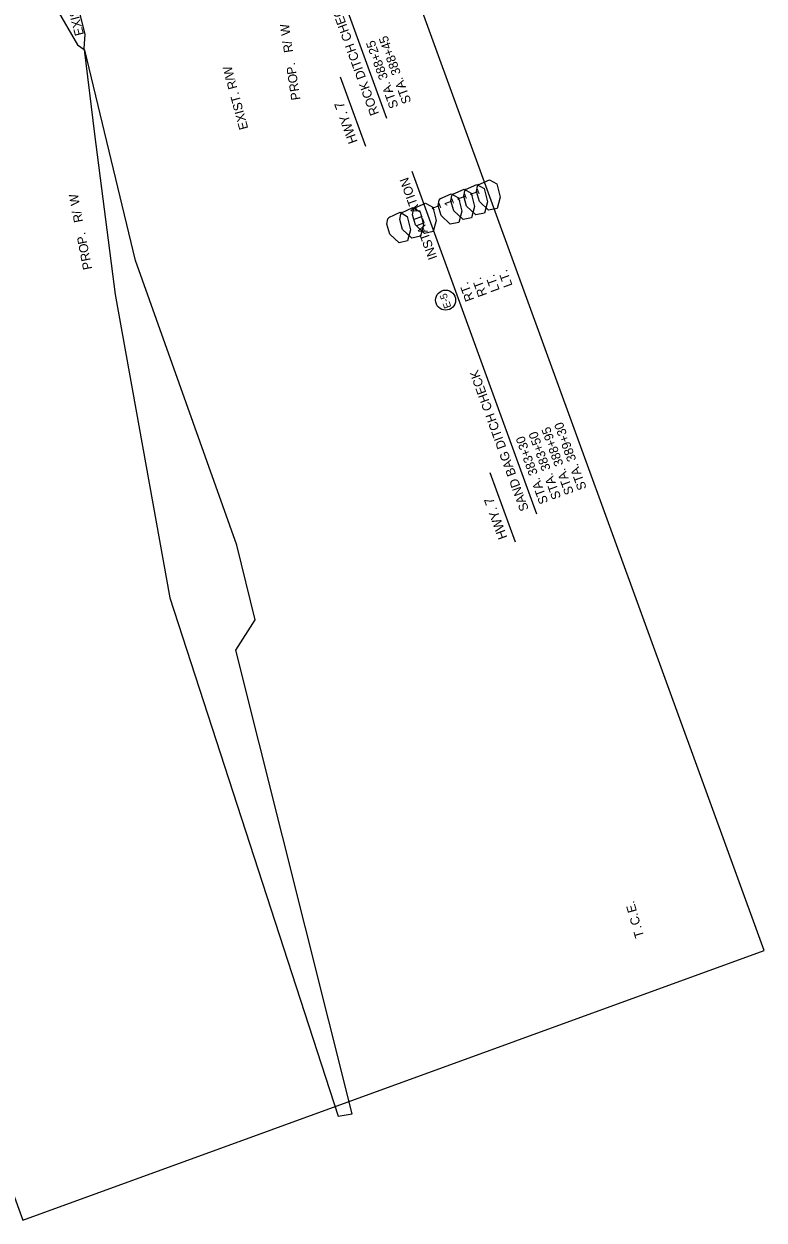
# Model space of a CAD drawing. Extents: x 960650 to 962115, y 1906901 to 1908930.
# Drawn here: x 961626 to 962115, y 1907079 to 1907870 of the extents above; entities that cross this region are included whole.
import ezdxf

# ---------------------------------------------------------------- set-up
doc = ezdxf.new("R2010")
doc.units = 0
for name, color, linetype in [('1', 7, 'Continuous'), ('44', 7, 'Continuous'), ('NO PLOT', 7, 'Continuous'), ('R_Draft', 7, 'Continuous'), ('S_TREE', 7, 'Continuous')]:
    doc.layers.add(name, color=color, linetype=linetype)

msp = doc.modelspace()

# ---------------------------------------------------------------- linework, layer by layer
at = {"layer": '1'}
msp.add_circle((961904.14, 1907687.38), 6.61, dxfattribs=at)
at = {"layer": '44'}
for p, q in [((961865.4, 1907807.44), (961782.97, 1908033.91)), ((961851.33, 1907788.82), (961834.62, 1907834.72)), ((961964.38, 1907545.95), (961881.95, 1907772.42)), ((961950.3, 1907527.33), (961933.6, 1907573.23))]:
    msp.add_line(p, q, dxfattribs=at)
at = {"layer": 'NO PLOT'}
msp.add_lwpolyline([(962114.55, 1907257.7), (961568.91, 1908756.85), (961079.18, 1908578.6), (961182.12, 1908295.76), (961245.55, 1908318.85), (961390.91, 1907919.48), (961327.48, 1907896.39), (961425.36, 1907627.47), (961483.4, 1907648.6), (961600.59, 1907326.6), (961542.56, 1907305.48), (961624.82, 1907079.46)], close=True, dxfattribs=at)
msp.add_lwpolyline([(962114.55, 1907257.7), (961568.91, 1908756.85), (961079.18, 1908578.6), (961182.12, 1908295.76), (961245.55, 1908318.85), (961390.91, 1907919.48), (961327.48, 1907896.39), (961425.36, 1907627.47), (961483.4, 1907648.6), (961600.59, 1907326.6), (961542.56, 1907305.48), (961624.82, 1907079.46)], close=True, dxfattribs=at)
msp.add_lwpolyline([(962114.55, 1907257.7), (961568.91, 1908756.85), (961079.18, 1908578.6), (961182.12, 1908295.76), (961245.55, 1908318.85), (961390.91, 1907919.48), (961327.48, 1907896.39), (961425.36, 1907627.47), (961483.4, 1907648.6), (961600.59, 1907326.6), (961542.56, 1907305.48), (961624.82, 1907079.46)], close=True, dxfattribs=at)
msp.add_lwpolyline([(961546.11, 1908053.77), (961660.88, 1907856.14), (961665.4, 1907852.91), (961665.4, 1907852.91), (961672.08, 1907797.08), (961685.77, 1907691.1), (961721.87, 1907490.67), (961833.17, 1907148.06), (961842.49, 1907149.72), (961765.53, 1907456.14), (961778.4, 1907476.17), (961766.21, 1907525.48), (961699.17, 1907713.63), (961665.82, 1907852.62), (961665.4, 1907852.91), (961665.4, 1907852.91), (961665.39, 1907852.96), (961665.26, 1907853.71), (961666.04, 1907863.2), (961658.05, 1907894.81)], dxfattribs=at)
at = {"layer": 'S_TREE'}
for points in [[(961908.82, 1907757.31), (961916.29, 1907760.79), (961921.12, 1907758.06), (961923.27, 1907749.23), (961921.34, 1907741.85), (961915.63, 1907740.58), (961909.55, 1907746.46), (961907.7, 1907752.91), (961908.31, 1907756.56), (961909.5, 1907757.78)], [(961908.82, 1907757.31), (961916.29, 1907760.79), (961921.12, 1907758.06), (961923.27, 1907749.23), (961921.34, 1907741.85), (961915.63, 1907740.58), (961909.55, 1907746.46), (961907.7, 1907752.91), (961908.31, 1907756.56), (961909.5, 1907757.78)], [(961908.82, 1907757.31), (961916.29, 1907760.79), (961921.12, 1907758.06), (961923.27, 1907749.23), (961921.34, 1907741.85), (961915.63, 1907740.58), (961909.55, 1907746.46), (961907.7, 1907752.91), (961908.31, 1907756.56), (961909.5, 1907757.78)], [(961908.82, 1907757.31), (961916.29, 1907760.79), (961921.12, 1907758.06), (961923.27, 1907749.23), (961921.34, 1907741.85), (961915.63, 1907740.58), (961909.55, 1907746.46), (961907.7, 1907752.91), (961908.31, 1907756.56), (961909.5, 1907757.78)], [(961917.28, 1907760.39), (961924.75, 1907763.87), (961929.58, 1907761.14), (961931.73, 1907752.31), (961929.79, 1907744.93), (961924.09, 1907743.66), (961918.01, 1907749.54), (961916.15, 1907755.99), (961916.77, 1907759.64), (961917.96, 1907760.86)], [(961917.28, 1907760.39), (961924.75, 1907763.87), (961929.58, 1907761.14), (961931.73, 1907752.31), (961929.79, 1907744.93), (961924.09, 1907743.66), (961918.01, 1907749.54), (961916.15, 1907755.99), (961916.77, 1907759.64), (961917.96, 1907760.86)], [(961917.28, 1907760.39), (961924.75, 1907763.87), (961929.58, 1907761.14), (961931.73, 1907752.31), (961929.79, 1907744.93), (961924.09, 1907743.66), (961918.01, 1907749.54), (961916.15, 1907755.99), (961916.77, 1907759.64), (961917.96, 1907760.86)], [(961917.28, 1907760.39), (961924.75, 1907763.87), (961929.58, 1907761.14), (961931.73, 1907752.31), (961929.79, 1907744.93), (961924.09, 1907743.66), (961918.01, 1907749.54), (961916.15, 1907755.99), (961916.77, 1907759.64), (961917.96, 1907760.86)], [(961925.73, 1907763.46), (961933.21, 1907766.95), (961938.04, 1907764.22), (961940.19, 1907755.39), (961938.25, 1907748.01), (961932.55, 1907746.73), (961926.47, 1907752.62), (961924.61, 1907759.06), (961925.22, 1907762.72), (961926.42, 1907763.94)], [(961925.73, 1907763.46), (961933.21, 1907766.95), (961938.04, 1907764.22), (961940.19, 1907755.39), (961938.25, 1907748.01), (961932.55, 1907746.73), (961926.47, 1907752.62), (961924.61, 1907759.06), (961925.22, 1907762.72), (961926.42, 1907763.94)], [(961900.36, 1907754.23), (961907.84, 1907757.72), (961912.66, 1907754.98), (961914.81, 1907746.15), (961912.88, 1907738.77), (961907.18, 1907737.5), (961901.1, 1907743.38), (961899.24, 1907749.83), (961899.85, 1907753.48), (961901.04, 1907754.71)], [(961900.36, 1907754.23), (961907.84, 1907757.72), (961912.66, 1907754.98), (961914.81, 1907746.15), (961912.88, 1907738.77), (961907.18, 1907737.5), (961901.1, 1907743.38), (961899.24, 1907749.83), (961899.85, 1907753.48), (961901.04, 1907754.71)], [(961900.36, 1907754.23), (961907.84, 1907757.72), (961912.66, 1907754.98), (961914.81, 1907746.15), (961912.88, 1907738.77), (961907.18, 1907737.5), (961901.1, 1907743.38), (961899.24, 1907749.83), (961899.85, 1907753.48), (961901.04, 1907754.71)], [(961900.36, 1907754.23), (961907.84, 1907757.72), (961912.66, 1907754.98), (961914.81, 1907746.15), (961912.88, 1907738.77), (961907.18, 1907737.5), (961901.1, 1907743.38), (961899.24, 1907749.83), (961899.85, 1907753.48), (961901.04, 1907754.71)], [(961866.53, 1907741.92), (961874.01, 1907745.4), (961878.84, 1907742.67), (961880.98, 1907733.84), (961879.05, 1907726.46), (961873.35, 1907725.19), (961867.27, 1907731.07), (961865.41, 1907737.52), (961866.02, 1907741.17), (961867.22, 1907742.39)], [(961866.53, 1907741.92), (961874.01, 1907745.4), (961878.84, 1907742.67), (961880.98, 1907733.84), (961879.05, 1907726.46), (961873.35, 1907725.19), (961867.27, 1907731.07), (961865.41, 1907737.52), (961866.02, 1907741.17), (961867.22, 1907742.39)], [(961874.99, 1907745), (961882.46, 1907748.48), (961887.29, 1907745.75), (961889.44, 1907736.92), (961887.51, 1907729.54), (961881.8, 1907728.27), (961875.72, 1907734.15), (961873.87, 1907740.6), (961874.48, 1907744.25), (961875.67, 1907745.47)], [(961874.99, 1907745), (961882.46, 1907748.48), (961887.29, 1907745.75), (961889.44, 1907736.92), (961887.51, 1907729.54), (961881.8, 1907728.27), (961875.72, 1907734.15), (961873.87, 1907740.6), (961874.48, 1907744.25), (961875.67, 1907745.47)], [(961883.45, 1907748.07), (961890.92, 1907751.56), (961895.75, 1907748.83), (961897.9, 1907740), (961895.96, 1907732.62), (961890.26, 1907731.34), (961884.18, 1907737.23), (961882.32, 1907743.67), (961882.94, 1907747.33), (961884.13, 1907748.55)], [(961883.45, 1907748.07), (961890.92, 1907751.56), (961895.75, 1907748.83), (961897.9, 1907740), (961895.96, 1907732.62), (961890.26, 1907731.34), (961884.18, 1907737.23), (961882.32, 1907743.67), (961882.94, 1907747.33), (961884.13, 1907748.55)]]:
    msp.add_lwpolyline(points, dxfattribs=at)

# ---------------------------------------------------------------- texts
at = {"layer": '1'}
msp.add_text('E-5 ', height=4.8, rotation=110, dxfattribs=at).set_placement((961907.99, 1907682.93))
at = {"layer": '44'}
for s, height, p in [('ROCK DITCH CHECK', 6, (961860.23, 1907810.66)), ('STA. 388+25', 6, (961873.08, 1907815.34)), ('STA. 388+45', 6, (961881.54, 1907818.42)), ('HWY. 7', 6.25, (961846.12, 1907792.08)), ('INSTALLATION', 6, (961898.72, 1907715.36)), ('1', 6, (961926.85, 1907757.05)), ('1', 6, (961909.93, 1907750.89)), ('1', 6, (961918.39, 1907753.97)), ('1', 6, (961901.48, 1907747.81)), ('LT.', 6, (961948.48, 1907697.14)), ('RT.', 6, (961923.15, 1907687.77)), ('RT.', 6, (961931.61, 1907690.85)), ('LT.', 6, (961940.02, 1907694.06)), ('SAND BAG DITCH CHECK', 6, (961959.21, 1907549.17)), ('STA. 388+95', 6, (961988.97, 1907560)), ('STA. 389+30', 6, (961997.43, 1907563.08)), ('STA. 383+30', 6, (961972.05, 1907553.85)), ('STA. 383+50', 6, (961980.51, 1907556.93)), ('HWY. 7', 6.25, (961945.09, 1907530.59))]:
    msp.add_text(s, height=height, rotation=110, dxfattribs=at).set_placement(p)
at = {"layer": 'R_Draft'}
for s, rotation, p in [('EXIST. R/W', 104.76842, (961665.25, 1907862.97)), ('W', 98.68221, (961801.69, 1907862.78)), ('/', 98.68221, (961802.58, 1907856.99)), ('R', 98.68221, (961803.43, 1907851.39)), ('EXIST. R/W', 105.0127, (961773.77, 1907800.88)), ('P', 98.68221, (961805.64, 1907836.96)), ('.', 98.68221, (961804.78, 1907842.56)), ('O', 98.68221, (961806.52, 1907831.17)), ('R', 98.68221, (961807.38, 1907825.56)), ('P', 98.68221, (961808.23, 1907819.96)), ('W', 100.8503, (961662.47, 1907750.58)), ('/', 100.8503, (961663.57, 1907744.83)), ('R', 100.8503, (961664.64, 1907739.26)), ('P', 100.8503, (961667.38, 1907724.93)), ('.', 100.8503, (961666.32, 1907730.49)), ('O', 100.8503, (961668.49, 1907719.17)), ('R', 100.8503, (961669.55, 1907713.6)), ('P', 100.8503, (961670.62, 1907708.04)), ('E', 105.81657, (962030.6, 1907283.5)), ('.', 105.81657, (962029.13, 1907288.68)), ('C', 105.81657, (962032.94, 1907275.23)), ('.', 105.81657, (962031.4, 1907280.68)), ('.', 105.81657, (962033.74, 1907272.41)), ('T', 105.81657, (962035.34, 1907266.78))]:
    msp.add_text(s, height=6, rotation=rotation, dxfattribs=at).set_placement(p)

doc.saveas('drawing.dxf')
